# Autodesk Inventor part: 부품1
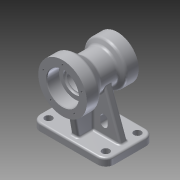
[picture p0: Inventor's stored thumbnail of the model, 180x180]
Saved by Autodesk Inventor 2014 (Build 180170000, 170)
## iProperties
Created: 2015-08
Part Number: 부품1
Material: 알루미늄 6061
Document SubType Name: Modeling
Designer: SCD-A08
Density: 2.71 g/cm^3
Appearance: 알루미늄 - 평지
Mass: 1077.91 g
Surface Area: 731.532 cm^2
Volume: 397.754 cm^3
Author: SCD-A08
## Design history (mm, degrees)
sketch "스케치6"
  geometry: L1 (-61, 40)-(61, 40); L2 (61, 40)-(61, -40); L3 (61, -40)-(-61, -40); L4 (-61, -40)-(-61, 40); 3 further points
  constraints: 8 end point, 2 midpoint, 2 parallel, 1 horizontal, 1 horizontal alignment, 1 perpendicular, 1 vertical alignment
  dimensions: "d32" = 122 distance of L1.start L1.end; "d33" = 80 distance of L1.end L2.end
extrude "돌출6" new body sketch "스케치6" distance "d34" = 12; taper "d35" = 0 deg
node "작업 평면3"
sketch "스케치7"
  geometry: L1 (0, 40)-(0, -50); L2 (0, 40)-(-35, 40); L3 (-35, 40)-(-35, 20); L4 (-35, 20)-(-26, 14.804); L5 (-26, 14.804)-(-26, -13.315); L6 (-26, -13.315)-(-40, -30); L7 (-40, -30)-(-40, -50); L8 (-40, -50)-(0, -50); L9 (-61, 40)-(61, 40) reference; 3 further points
  constraints: 16 end point, 3 perpendicular, 2 coincident, 2 midpoint, 2 parallel, 1 vertical
  dimensions: "d37" = 90 distance of L1.start L1.end; "d38" = 20 distance of L2.end L3.end; "d39" = 20 distance of L6.end L7.end; "d40" = 70 diameter of L3 L1; "d41" = 80 diameter of L7 L1; "d42" = 52 diameter of L5 L1; "d43" = 60 deg angle of L5 L4; "d44" = 40 deg angle of L6 L5
revolve "회전2" sketch "스케치7" stored, may be unused: angle "d45" = 90 deg
sketch "스케치8"
  geometry: L1 (-61, 12)-(61, 12) reference; L2 (-25.091, 83.185)-(-51, 12); L3 (0, 90)-(0, 0); L4 (25.091, 83.185)-(51, 12); L5 (51, 12)-(-51, 12); A1 r 26 centre (0, 90) between (-25.091, 83.185) and (25.091, 83.185)
  constraints: 8 end point, 2 point on circle, 2 symmetric about line, 1 centre point, 1 coincident, 1 collinear, 1 perpendicular, 1 point on line, 2 other
  dimensions: "d46" = 10 distance of L1.start L2.end; "d47" = 70 deg angle of L1 L2
extrude "돌출7" join sketch "스케치8" stored distance "d48" = 12; taper "d49" = 0 deg
sketch "스케치9"
  geometry: L1 (-40, 12)-(40, 12) reference; L2 (30, 12)-(30, 90); L3 (30, 90)-(-43.754, 90); L4 (-43.754, 90)-(-30, 12); L5 (30, 12)-(-30, 12); 1 further point
  constraints: 8 end point, 2 perpendicular, 2 point on line, 1 collinear
  dimensions: "d50" = 10 distance of L2.start L1.end; "d51" = 10 distance of L1.start L4.end; "d52" = 80 deg angle of L1 L4; "d53" = 78 distance of L2.start L2.end
extrude "돌출8" join sketch "스케치9" stored distance "d54" = 12; taper "d55" = 0 deg
sketch "스케치10"
  geometry: L1 (-50, 50)-(-50, 130) reference; L2 (-50, 90)-(40, 90); L3 (-50, 116)-(-30, 116); L4 (-30, 116)-(-30, 109); L5 (-30, 109)-(-30, 109); L6 (-27, 106)-(-27, 106); L7 (-27, 106)-(23, 106); L8 (23, 106)-(23, 110); L9 (40, 55)-(40, 125) reference; L10 (23, 110)-(40, 110); L11 (-50, 116)-(-50, 90); L12 (40, 110)-(40, 90); A1 r 3 centre (-30, 106) between (-27, 106) and (-30, 109); 2 further points
  constraints: 20 end point, 5 parallel, 4 point on line, 3 perpendicular, 2 midpoint, 2 point on circle, 2 tangent, 1 centre point, 1 collinear
  dimensions: "d56" = 52 diameter of L3 L2; "d57" = 20 distance of L3.start L3.end; "d58" = 38 diameter of L5 L2; "d59" = 3 distance of L4.end point (-27, 109); "d60" = 32 diameter of L7 L2; "d61" = 17 distance of L8.end L10.end; "d62" = 40 diameter of L10 L2; "d63" = 3 radius of A1
revolve "회전3" sketch "스케치10" stored, may be unused: angle "d64" = 90 deg
chamfer "모따기1" distance "d65" = 1; stored, may be unused: second distance "d66" = 2, angle "d67" = 45 deg
fillet "모깎기1" dims "d68" = 0.3
fillet "모깎기2" dims "d69" = 14
sketch "스케치11"
  geometry: A1 r 14 centre (-47, 26) between (-47, 40) and (-61, 26) reference; 2 further points
  constraints: 1 coincident
hole "구멍1" sketch "스케치11" at (-47, 26) diameter "d70" = 12; stored, may be unused: countersink angle "d74" = 90 deg, drill point angle "d76" = 118 deg; dims "d71" = 6, "d72" = 4, "d73" = 2, "d75" = 8
sketch "스케치12"
  geometry: C1 r 35 at (0, 0) reference; 2 further points
  constraints: 1 vertical alignment
  dimensions: "d85" = 27 distance of C1.centre point (0, -27)
hole "구멍2" sketch "스케치12" at (0, -27) diameter "d86" = 3.242; stored, may be unused: countersink angle "d90" = 90 deg, drill point angle "d92" = 118 deg; dims "d87" = 10, "d88" = 4, "d89" = 2, "d91" = 13
sketch "스케치13"
  geometry: C1 r 40 at (0, 0) reference; 3 further points
  constraints: 1 coincident, 1 vertical alignment
  dimensions: "d96" = 33 distance of point (0, 33) C1.centre
hole "구멍3" sketch "스케치13" at (0, 33) diameter "d97" = 3.242; stored, may be unused: countersink angle "d101" = 90 deg, drill point angle "d103" = 118 deg; dims "d98" = 10, "d99" = 4, "d100" = 2, "d102" = 13
sketch "스케치14"
  geometry: L1 (12, 30)-(55.518, 30) reference; L2 (12, 30)-(12, 6) reference; 2 further points
  constraints: 1 other
  dimensions: "d122" = 16 distance from line of point (36, 14) L1; "d123" = 24 distance from line of point (36, 14) L2
feature "엠보싱1" sketch "스케치14" dims "d32" = 122, "d33" = 80, "d109" = 0.5, "d110" = 0
sketch "스케치15"
  geometry: L1 (24, 37)-(24, 30); L2 (18, 37)-(18, 30); L3 (30, 30)-(30, 37); L4 (-6, 12)-(-6, 64.702) reference; L5 (-6, 12)-(-51, 12) reference; A1 r 6 centre (24, 37) between (30, 37) and (18, 37); A2 r 6 centre (24, 30) between (18, 30) and (30, 30); 2 further points
  constraints: 8 end point, 4 point on circle, 4 tangent, 2 centre point, 2 parallel, 1 midpoint
  dimensions: "d112" = 12 distance between parallel lines of L3 L2; "d113" = 7 distance of L1.end L1.start; "d114" = 24 horizontal distance of point (24, 33.5) point (0, 0); "d121" = 18 distance from line of L1.end L5
extrude "돌출9" cut sketch "스케치15" stored distance "d116" = 10; taper "d117" = 0 deg
fillet "모깎기5" dims "d118" = 3
fillet "모깎기6" dims "d119" = 5
fillet "모깎기7" dims "d120" = 3
node "솔리드2"
pattern_linear "직사각형 패턴1" dims "d79" = 94, "d82" = 52
pattern_circular "원형 패턴1" dims angle "d94" = 360 deg
pattern_circular "원형 패턴2" dims angle "d105" = 360 deg
mirror "대칭2"
